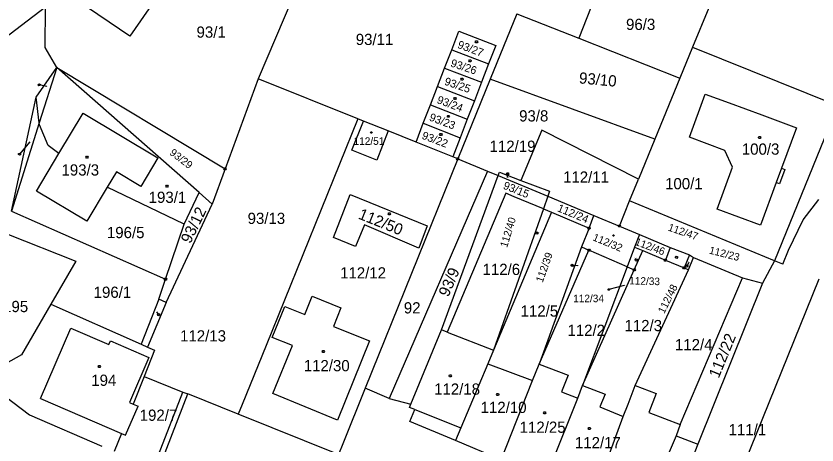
# Model space of a CAD drawing. Extents: x -634640 to -629202, y -1196156 to -1190068.
# Drawn here: x -631489.7 to -631368.4, y -1192793.1 to -1192728.1 of the extents above; entities that cross this region are included whole.
import ezdxf

# ---------------------------------------------------------------- set-up
doc = ezdxf.new("R2010")
doc.units = 0
for name, color, linetype in [('Vrstva 1', 7, 'Continuous'), ('Vrstva 2', 7, 'Continuous'), ('Vrstva 3', 7, 'Continuous'), ('Vrstva 4', 7, 'Continuous'), ('Vrstva 5', 7, 'Continuous'), ('Vrstva 7', 7, 'Continuous'), ('Vrstva 8', 7, 'Continuous')]:
    doc.layers.add(name, color=color, linetype=linetype)

msp = doc.modelspace()

# ---------------------------------------------------------------- linework, layer by layer
at = {"layer": 'Vrstva 1'}
for p, q in [((-631400.34, -1192720.95), (-631404.48, -1192731.49)), ((-631446.43, -1192722.09), (-631453.01, -1192737.63)), ((-631498.79, -1192737.08), (-631485.2, -1192726.74)), ((-631485.26, -1192732.88), (-631485.2, -1192726.74)), ((-631384.81, -1192726.88), (-631387.28, -1192732.83)), ((-631413.88, -1192727.78), (-631417.89, -1192737.71)), ((-631413.88, -1192727.78), (-631404.48, -1192731.49)), ((-631423.71, -1192733.23), (-631422.63, -1192730.43)), ((-631422.63, -1192730.43), (-631417.06, -1192732.57)), ((-631404.48, -1192731.49), (-631389.22, -1192737.52)), ((-631483.51, -1192735.91), (-631485.26, -1192732.88)), ((-631424.79, -1192736.02), (-631423.71, -1192733.23)), ((-631423.71, -1192733.23), (-631418.14, -1192735.39)), ((-631417.06, -1192732.57), (-631418.14, -1192735.39)), ((-631387.28, -1192732.83), (-631389.22, -1192737.52)), ((-631387.28, -1192732.83), (-631365.33, -1192741.7)), ((-631486.64, -1192740.44), (-631483.51, -1192735.91)), ((-631483.51, -1192735.91), (-631486.14, -1192744.29)), ((-631483.51, -1192735.91), (-631458.03, -1192751.28)), ((-631461.95, -1192754.88), (-631483.51, -1192735.91)), ((-631418.14, -1192735.39), (-631419.21, -1192738.17)), ((-631425.86, -1192738.79), (-631424.79, -1192736.02)), ((-631424.79, -1192736.02), (-631419.21, -1192738.17)), ((-631453.01, -1192737.63), (-631458.03, -1192751.28)), ((-631437.91, -1192743.69), (-631453.01, -1192737.63)), ((-631417.89, -1192737.71), (-631422.82, -1192749.75)), ((-631419.21, -1192738.17), (-631420.28, -1192740.95)), ((-631392.98, -1192746.79), (-631417.89, -1192737.71)), ((-631389.22, -1192737.52), (-631392.98, -1192746.79)), ((-631426.94, -1192741.6), (-631425.86, -1192738.79)), ((-631425.86, -1192738.79), (-631420.28, -1192740.95)), ((-631490.35, -1192757.69), (-631486.64, -1192740.44)), ((-631486.14, -1192744.29), (-631486.64, -1192740.44)), ((-631387.75, -1192746.48), (-631385.35, -1192739.94)), ((-631385.35, -1192739.94), (-631381.73, -1192741.27)), ((-631428.02, -1192744.38), (-631426.94, -1192741.6)), ((-631426.94, -1192741.6), (-631421.36, -1192743.76)), ((-631420.28, -1192740.95), (-631421.36, -1192743.76)), ((-631381.73, -1192741.27), (-631376.81, -1192743.11)), ((-631365.33, -1192741.7), (-631374.86, -1192765.19)), ((-631376.81, -1192743.11), (-631371.55, -1192745.07)), ((-631486.14, -1192744.29), (-631490.35, -1192757.69)), ((-631486.1, -1192744.61), (-631486.14, -1192744.29)), ((-631437.91, -1192743.69), (-631451.81, -1192778.03)), ((-631438.85, -1192748.46), (-631437.07, -1192744.03)), ((-631437.07, -1192744.03), (-631437.91, -1192743.69)), ((-631433.32, -1192745.53), (-631437.07, -1192744.03)), ((-631429.11, -1192747.22), (-631428.02, -1192744.38)), ((-631428.02, -1192744.38), (-631422.43, -1192746.57)), ((-631421.36, -1192743.76), (-631422.43, -1192746.57)), ((-631484.8, -1192747.76), (-631486.1, -1192744.61)), ((-631433.32, -1192745.53), (-631435.06, -1192749.97)), ((-631429.11, -1192747.22), (-631433.32, -1192745.53)), ((-631410.08, -1192745.42), (-631413.24, -1192753.02)), ((-631395.43, -1192752.83), (-631410.08, -1192745.42)), ((-631371.55, -1192745.07), (-631373.8, -1192751.19)), ((-631422.43, -1192746.57), (-631423.54, -1192749.46)), ((-631392.98, -1192746.79), (-631395.43, -1192752.83)), ((-631382.39, -1192748.49), (-631387.75, -1192746.48)), ((-631483.17, -1192748.95), (-631484.8, -1192747.76)), ((-631423.54, -1192749.46), (-631429.11, -1192747.22)), ((-631435.06, -1192749.97), (-631438.85, -1192748.46)), ((-631381.23, -1192751.01), (-631382.39, -1192748.49)), ((-631422.82, -1192749.75), (-631436.8, -1192784.5)), ((-631422.82, -1192749.75), (-631423.54, -1192749.46)), ((-631422.82, -1192749.75), (-631418.32, -1192751.62)), ((-631458.03, -1192751.28), (-631459.99, -1192756.61)), ((-631418.32, -1192751.62), (-631433.21, -1192786.06)), ((-631418.32, -1192751.62), (-631416.69, -1192752.3)), ((-631383.55, -1192757.36), (-631381.23, -1192751.01)), ((-631373.31, -1192751.35), (-631374.1, -1192753.52)), ((-631373.8, -1192751.19), (-631373.31, -1192751.35)), ((-631425.27, -1192775.67), (-631416.69, -1192752.3)), ((-631416.69, -1192752.3), (-631416.5, -1192751.78)), ((-631416.69, -1192752.3), (-631409.17, -1192755.43)), ((-631416.5, -1192751.78), (-631413.24, -1192753.02)), ((-631396.8, -1192756.14), (-631395.43, -1192752.83)), ((-631475.85, -1192754.07), (-631478.93, -1192759.2)), ((-631464.23, -1192759.66), (-631475.85, -1192754.07)), ((-631413.24, -1192753.02), (-631408.9, -1192754.67)), ((-631374.6, -1192753.36), (-631376.97, -1192759.79)), ((-631374.1, -1192753.52), (-631374.6, -1192753.36)), ((-631464.23, -1192759.66), (-631461.95, -1192754.88)), ((-631459.99, -1192756.61), (-631461.95, -1192754.88)), ((-631441.61, -1192761.66), (-631439.07, -1192755.18)), ((-631439.07, -1192755.18), (-631427.43, -1192759.9)), ((-631415.55, -1192754.95), (-631424.39, -1192776.02)), ((-631414.27, -1192755.49), (-631415.55, -1192754.95)), ((-631408.9, -1192754.67), (-631409.17, -1192755.43)), ((-631409.85, -1192757.34), (-631414.27, -1192755.49)), ((-631409.17, -1192755.43), (-631409.85, -1192757.34)), ((-631409.17, -1192755.43), (-631402.19, -1192758.33)), ((-631398.35, -1192759.93), (-631396.8, -1192756.14)), ((-631374.86, -1192765.19), (-631396.8, -1192756.14)), ((-631370.55, -1192759.01), (-631368.15, -1192755.91)), ((-631490.35, -1192757.69), (-631467.04, -1192767.99)), ((-631466.96, -1192771.5), (-631459.99, -1192756.61)), ((-631409.85, -1192757.34), (-631417.4, -1192778.73)), ((-631409.85, -1192757.34), (-631408.64, -1192757.85)), ((-631376.97, -1192759.79), (-631383.55, -1192757.36)), ((-631408.64, -1192757.85), (-631417.4, -1192778.73)), ((-631408.64, -1192757.85), (-631402.93, -1192760.24)), ((-631402.93, -1192760.24), (-631402.19, -1192758.33)), ((-631402.19, -1192758.33), (-631398.35, -1192759.93)), ((-631372.74, -1192763.57), (-631370.55, -1192759.01)), ((-631467.04, -1192767.99), (-631464.23, -1192759.66)), ((-631436.9, -1192759.76), (-631438.26, -1192763.05)), ((-631428.71, -1192763.29), (-631436.9, -1192759.76)), ((-631427.43, -1192759.9), (-631428.71, -1192763.29)), ((-631398.35, -1192759.93), (-631395.31, -1192761.21)), ((-631491.08, -1192761.11), (-631480.61, -1192765.27)), ((-631402.93, -1192760.24), (-631404.06, -1192763.1)), ((-631395.31, -1192761.21), (-631396.04, -1192763.13)), ((-631395.31, -1192761.21), (-631390.68, -1192763.18)), ((-631438.26, -1192763.05), (-631441.61, -1192761.66)), ((-631404.06, -1192763.1), (-631410.49, -1192780.87)), ((-631410.49, -1192780.87), (-631402.95, -1192763.59)), ((-631404.06, -1192763.1), (-631402.95, -1192763.59)), ((-631397.17, -1192766.12), (-631402.95, -1192763.59)), ((-631396.04, -1192763.13), (-631397.17, -1192766.12)), ((-631396.1, -1192766.55), (-631394.8, -1192763.65)), ((-631396.04, -1192763.13), (-631394.8, -1192763.65)), ((-631394.8, -1192763.65), (-631391.39, -1192765.08)), ((-631390.68, -1192763.18), (-631391.39, -1192765.08)), ((-631390.68, -1192763.18), (-631387.72, -1192764.3)), ((-631373.61, -1192765.71), (-631372.74, -1192763.57)), ((-631391.39, -1192765.08), (-631388.54, -1192766.27)), ((-631387.72, -1192764.3), (-631388.54, -1192766.27)), ((-631387.88, -1192766.55), (-631387.11, -1192764.71)), ((-631387.72, -1192764.3), (-631387.11, -1192764.71)), ((-631387.11, -1192764.71), (-631379.73, -1192767.8)), ((-631480.61, -1192765.27), (-631484.4, -1192771.78)), ((-631397.17, -1192766.12), (-631403.94, -1192784.07)), ((-631397.17, -1192766.12), (-631396.1, -1192766.55)), ((-631388.54, -1192766.27), (-631387.88, -1192766.55)), ((-631374.86, -1192765.19), (-631376.69, -1192768.59)), ((-631373.61, -1192765.71), (-631374.86, -1192765.19)), ((-631403.94, -1192784.07), (-631396.1, -1192766.55)), ((-631395.95, -1192784.07), (-631387.88, -1192766.55)), ((-631468.06, -1192771.03), (-631467.04, -1192767.99)), ((-631389.17, -1192790), (-631379.73, -1192767.8)), ((-631376.69, -1192768.59), (-631386.47, -1192792.97)), ((-631368.14, -1192767.96), (-631383.56, -1192806)), ((-631379.73, -1192767.8), (-631376.69, -1192768.59)), ((-631468.06, -1192771.03), (-631470.7, -1192777.85)), ((-631466.96, -1192771.5), (-631468.06, -1192771.03)), ((-631445.97, -1192773.35), (-631444.86, -1192770.56)), ((-631444.86, -1192770.56), (-631440.48, -1192772.32)), ((-631484.4, -1192771.78), (-631488.86, -1192779.43)), ((-631484.4, -1192771.78), (-631470.7, -1192777.85)), ((-631466.96, -1192771.5), (-631469.75, -1192778.27)), ((-631450.89, -1192776.82), (-631448.99, -1192772.12)), ((-631448.99, -1192772.12), (-631445.97, -1192773.35)), ((-631440.48, -1192772.32), (-631441.6, -1192775.13)), ((-631441.6, -1192775.13), (-631436.15, -1192777.34)), ((-631429.91, -1192786.93), (-631425.27, -1192775.67)), ((-631424.39, -1192776.02), (-631425.27, -1192775.67)), ((-631447.84, -1192778.03), (-631450.89, -1192776.82)), ((-631424.39, -1192776.02), (-631417.4, -1192778.73)), ((-631470.7, -1192777.85), (-631469.75, -1192778.27)), ((-631469.75, -1192778.27), (-631468.69, -1192778.74)), ((-631451.81, -1192778.03), (-631455.42, -1192786.96)), ((-631450.82, -1192785.29), (-631447.84, -1192778.03)), ((-631436.15, -1192777.34), (-631441.02, -1192789.32)), ((-631488.86, -1192779.43), (-631492.05, -1192781.28)), ((-631468.69, -1192778.74), (-631470.27, -1192782.71)), ((-631417.4, -1192778.73), (-631418.27, -1192780.81)), ((-631418.27, -1192780.81), (-631422.34, -1192790.52)), ((-631418.27, -1192780.81), (-631411.52, -1192783.35)), ((-631411.52, -1192783.35), (-631410.49, -1192780.87)), ((-631470.27, -1192782.71), (-631471.93, -1192786.9)), ((-631470.27, -1192782.71), (-631464.4, -1192785.07)), ((-631493.95, -1192783.7), (-631487.64, -1192788.54)), ((-631416.22, -1192795.33), (-631411.52, -1192783.35)), ((-631404.64, -1192786.02), (-631403.94, -1192784.07)), ((-631468.1, -1192794.59), (-631464.4, -1192785.07)), ((-631467.72, -1192795.79), (-631463.65, -1192785.37)), ((-631464.4, -1192785.07), (-631463.65, -1192785.37)), ((-631456.02, -1192788.44), (-631463.65, -1192785.37)), ((-631441.02, -1192789.32), (-631450.82, -1192785.29)), ((-631436.8, -1192784.5), (-631440.19, -1192792.93)), ((-631433.21, -1192786.06), (-631436.8, -1192784.5)), ((-631471.93, -1192786.9), (-631471.2, -1192787.21)), ((-631433.21, -1192786.06), (-631429.91, -1192786.93)), ((-631409.38, -1192797.8), (-631404.64, -1192786.02)), ((-631473.1, -1192791.63), (-631471.2, -1192787.21)), ((-631455.42, -1192786.96), (-631456.02, -1192788.44)), ((-631430.12, -1192787.42), (-631429.91, -1192786.93)), ((-631429.31, -1192787.74), (-631430.12, -1192787.42)), ((-631430.06, -1192789.53), (-631429.31, -1192787.74)), ((-631487.64, -1192788.54), (-631476.67, -1192793.27)), ((-631440.84, -1192794.55), (-631456.02, -1192788.44)), ((-631401.38, -1192798.66), (-631397.78, -1192788.77)), ((-631423.14, -1192792.43), (-631430.06, -1192789.53)), ((-631422.34, -1192790.52), (-631423.14, -1192792.43)), ((-631389.17, -1192790), (-631389.76, -1192791.7)), ((-631473.71, -1192791.36), (-631474.79, -1192794.08)), ((-631473.71, -1192791.36), (-631473.1, -1192791.63)), ((-631389.76, -1192791.7), (-631394, -1192801.72)), ((-631389.76, -1192791.7), (-631386.47, -1192792.97)), ((-631440.19, -1192792.93), (-631440.84, -1192794.55)), ((-631416.22, -1192795.33), (-631423.14, -1192792.43)), ((-631386.47, -1192792.97), (-631390.43, -1192803.2))]:
    msp.add_line(p, q, dxfattribs=at)
for points in [[(-631470.12, -1192710.93), (-631462.2, -1192716.4), (-631472.46, -1192731.17), (-631480.39, -1192725.76), (-631470.12, -1192710.93)], [(-631483.17, -1192748.95), (-631479.51, -1192742.85), (-631468.21, -1192749.62), (-631470.79, -1192753.93), (-631474.45, -1192751.74), (-631475.85, -1192754.07)], [(-631478.93, -1192759.2), (-631486.58, -1192754.63), (-631483.17, -1192748.95)], [(-631410.49, -1192780.87), (-631406.08, -1192782.52), (-631407.09, -1192785.04), (-631404.64, -1192786.02)], [(-631403.94, -1192784.07), (-631400.5, -1192785.38), (-631401.3, -1192787.31), (-631397.78, -1192788.77)], [(-631397.78, -1192788.77), (-631397.04, -1192786.92), (-631395.95, -1192784.07)], [(-631395.95, -1192784.07), (-631392.76, -1192785.31), (-631393.87, -1192788.18), (-631389.17, -1192790)]]:
    msp.add_lwpolyline(points, dxfattribs=at)
at = {"layer": 'Vrstva 3'}
msp.add_lwpolyline([(-631466.72, -1192753.73), (-631466.63, -1192753.88), (-631466.72, -1192754.03), (-631466.9, -1192754.03), (-631466.99, -1192753.88), (-631466.9, -1192753.73), (-631466.72, -1192753.73)], dxfattribs=at)
at = {"layer": 'Vrstva 4'}
for p, q in [((-631373.8, -1192751.19), (-631374.6, -1192753.36)), ((-631485.98, -1192786.06), (-631481.38, -1192775.4)), ((-631481.38, -1192775.4), (-631475.62, -1192777.88)), ((-631475.62, -1192777.88), (-631475.38, -1192777.3)), ((-631475.38, -1192777.3), (-631469.54, -1192779.82)), ((-631469.54, -1192779.82), (-631472.48, -1192786.66)), ((-631485.98, -1192786.06), (-631473.71, -1192791.36)), ((-631472.48, -1192786.66), (-631471.93, -1192786.9)), ((-631429.31, -1192787.74), (-631422.34, -1192790.52))]:
    msp.add_line(p, q, dxfattribs=at)
at = {"layer": 'Vrstva 5'}
for points in [[(-631419.88, -1192731.9), (-631419.79, -1192732.05), (-631419.88, -1192732.2), (-631420.06, -1192732.2), (-631420.15, -1192732.05), (-631420.06, -1192731.9), (-631419.88, -1192731.9)], [(-631420.85, -1192734.75), (-631420.76, -1192734.9), (-631420.85, -1192735.05), (-631421.03, -1192735.05), (-631421.12, -1192734.9), (-631421.03, -1192734.75), (-631420.85, -1192734.75)], [(-631422.06, -1192737.52), (-631421.97, -1192737.67), (-631422.06, -1192737.82), (-631422.24, -1192737.82), (-631422.33, -1192737.67), (-631422.24, -1192737.52), (-631422.06, -1192737.52)], [(-631423.13, -1192740.45), (-631423.04, -1192740.6), (-631423.13, -1192740.75), (-631423.31, -1192740.75), (-631423.4, -1192740.6), (-631423.31, -1192740.45), (-631423.13, -1192740.45)], [(-631424.15, -1192743.17), (-631424.06, -1192743.32), (-631424.15, -1192743.47), (-631424.33, -1192743.47), (-631424.42, -1192743.32), (-631424.33, -1192743.17), (-631424.15, -1192743.17)], [(-631435.83, -1192745.67), (-631435.769, -1192745.77), (-631435.83, -1192745.87), (-631435.95, -1192745.87), (-631436.011, -1192745.77), (-631435.95, -1192745.67), (-631435.83, -1192745.67)], [(-631425.28, -1192745.93), (-631425.19, -1192746.08), (-631425.28, -1192746.23), (-631425.46, -1192746.23), (-631425.55, -1192746.08), (-631425.46, -1192745.93), (-631425.28, -1192745.93)], [(-631377.04, -1192746.39), (-631376.95, -1192746.54), (-631377.04, -1192746.69), (-631377.22, -1192746.69), (-631377.31, -1192746.54), (-631377.22, -1192746.39), (-631377.04, -1192746.39)], [(-631478.84, -1192749.34), (-631478.75, -1192749.49), (-631478.84, -1192749.64), (-631479.02, -1192749.64), (-631479.11, -1192749.49), (-631479.02, -1192749.34), (-631478.84, -1192749.34)], [(-631433.08, -1192757.94), (-631432.99, -1192758.09), (-631433.08, -1192758.24), (-631433.26, -1192758.24), (-631433.35, -1192758.09), (-631433.26, -1192757.94), (-631433.08, -1192757.94)], [(-631399.18, -1192761.27), (-631399.119, -1192761.37), (-631399.18, -1192761.47), (-631399.3, -1192761.47), (-631399.361, -1192761.37), (-631399.3, -1192761.27), (-631399.18, -1192761.27)], [(-631443.07, -1192778.78), (-631442.98, -1192778.93), (-631443.07, -1192779.08), (-631443.25, -1192779.08), (-631443.34, -1192778.93), (-631443.25, -1192778.78), (-631443.07, -1192778.78)], [(-631476.97, -1192781.07), (-631476.88, -1192781.22), (-631476.97, -1192781.37), (-631477.15, -1192781.37), (-631477.24, -1192781.22), (-631477.15, -1192781.07), (-631476.97, -1192781.07)], [(-631423.86, -1192782.49), (-631423.77, -1192782.64), (-631423.86, -1192782.79), (-631424.04, -1192782.79), (-631424.13, -1192782.64), (-631424.04, -1192782.49), (-631423.86, -1192782.49)], [(-631416.66, -1192785.31), (-631416.57, -1192785.46), (-631416.66, -1192785.61), (-631416.84, -1192785.61), (-631416.93, -1192785.46), (-631416.84, -1192785.31), (-631416.66, -1192785.31)], [(-631409.57, -1192788.08), (-631409.48, -1192788.23), (-631409.57, -1192788.38), (-631409.75, -1192788.38), (-631409.84, -1192788.23), (-631409.75, -1192788.08), (-631409.57, -1192788.08)], [(-631402.79, -1192790.43), (-631402.7, -1192790.58), (-631402.79, -1192790.73), (-631402.97, -1192790.73), (-631403.06, -1192790.58), (-631402.97, -1192790.43), (-631402.79, -1192790.43)]]:
    msp.add_lwpolyline(points, dxfattribs=at)
at = {"layer": 'Vrstva 7'}
for p, q in [((-631485.02, -1192738.82), (-631486.15, -1192738.55)), ((-631487.59, -1192747.16), (-631489.13, -1192749.05)), ((-631415.27, -1192752.6), (-631415.27, -1192752.05)), ((-631410.58, -1192761.01), (-631410.84, -1192761.01)), ((-631395.97, -1192764.83), (-631395.77, -1192765.07)), ((-631389.73, -1192764.76), (-631389.7, -1192764.66)), ((-631404.62, -1192765.96), (-631405.48, -1192765.9)), ((-631387.85, -1192765.45), (-631388.13, -1192766)), ((-631397.6, -1192768.95), (-631399.94, -1192769.54)), ((-631468.4, -1192772.94), (-631468.08, -1192773.36))]:
    msp.add_line(p, q, dxfattribs=at)
for points in [[(-631486.275, -1192738.428), (-631486.109, -1192738.375), (-631485.983, -1192738.497), (-631486.025, -1192738.672), (-631486.191, -1192738.725), (-631486.317, -1192738.603), (-631486.275, -1192738.428)], [(-631489.295, -1192749.109), (-631489.269, -1192748.936), (-631489.105, -1192748.877), (-631488.965, -1192748.991), (-631488.991, -1192749.164), (-631489.155, -1192749.223), (-631489.295, -1192749.109)], [(-631415.18, -1192751.9), (-631415.09, -1192752.05), (-631415.18, -1192752.2), (-631415.36, -1192752.2), (-631415.45, -1192752.05), (-631415.36, -1192751.9), (-631415.18, -1192751.9)], [(-631410.99, -1192760.92), (-631410.84, -1192760.83), (-631410.69, -1192760.92), (-631410.69, -1192761.1), (-631410.84, -1192761.19), (-631410.99, -1192761.1), (-631410.99, -1192760.92)], [(-631395.748, -1192765.244), (-631395.912, -1192765.181), (-631395.933, -1192765.008), (-631395.792, -1192764.896), (-631395.628, -1192764.959), (-631395.607, -1192765.132), (-631395.748, -1192765.244)], [(-631389.564, -1192764.55), (-631389.531, -1192764.722), (-631389.667, -1192764.832), (-631389.836, -1192764.77), (-631389.869, -1192764.598), (-631389.733, -1192764.488), (-631389.564, -1192764.55)], [(-631405.624, -1192765.801), (-631405.469, -1192765.72), (-631405.325, -1192765.82), (-631405.336, -1192765.999), (-631405.491, -1192766.08), (-631405.635, -1192765.98), (-631405.624, -1192765.801)], [(-631388.279, -1192766.092), (-631388.29, -1192765.917), (-631388.141, -1192765.825), (-631387.981, -1192765.908), (-631387.97, -1192766.083), (-631388.119, -1192766.175), (-631388.279, -1192766.092)], [(-631400.052, -1192769.506), (-631399.969, -1192769.423), (-631399.857, -1192769.457), (-631399.828, -1192769.574), (-631399.911, -1192769.657), (-631400.023, -1192769.623), (-631400.052, -1192769.506)], [(-631468.059, -1192773.534), (-631468.222, -1192773.471), (-631468.243, -1192773.297), (-631468.101, -1192773.186), (-631467.938, -1192773.249), (-631467.917, -1192773.423), (-631468.059, -1192773.534)]]:
    msp.add_lwpolyline(points, dxfattribs=at)
at = {"layer": 'Vrstva 8'}
for points in [[(-631422.73, -1192749.6), (-631422.64, -1192749.75), (-631422.73, -1192749.9), (-631422.91, -1192749.9), (-631423, -1192749.75), (-631422.91, -1192749.6), (-631422.73, -1192749.6)], [(-631457.94, -1192751.13), (-631457.85, -1192751.28), (-631457.94, -1192751.43), (-631458.12, -1192751.43), (-631458.21, -1192751.28), (-631458.12, -1192751.13), (-631457.94, -1192751.13)], [(-631402.84, -1192760.09), (-631402.75, -1192760.24), (-631402.84, -1192760.39), (-631403.02, -1192760.39), (-631403.11, -1192760.24), (-631403.02, -1192760.09), (-631402.84, -1192760.09)], [(-631398.26, -1192759.78), (-631398.17, -1192759.93), (-631398.26, -1192760.08), (-631398.44, -1192760.08), (-631398.53, -1192759.93), (-631398.44, -1192759.78), (-631398.26, -1192759.78)], [(-631402.86, -1192763.44), (-631402.77, -1192763.59), (-631402.86, -1192763.74), (-631403.04, -1192763.74), (-631403.13, -1192763.59), (-631403.04, -1192763.44), (-631402.86, -1192763.44)], [(-631391.3, -1192764.93), (-631391.21, -1192765.08), (-631391.3, -1192765.23), (-631391.48, -1192765.23), (-631391.57, -1192765.08), (-631391.48, -1192764.93), (-631391.3, -1192764.93)], [(-631388.45, -1192766.12), (-631388.36, -1192766.27), (-631388.45, -1192766.42), (-631388.63, -1192766.42), (-631388.72, -1192766.27), (-631388.63, -1192766.12), (-631388.45, -1192766.12)], [(-631396.01, -1192766.4), (-631395.92, -1192766.55), (-631396.01, -1192766.7), (-631396.19, -1192766.7), (-631396.28, -1192766.55), (-631396.19, -1192766.4), (-631396.01, -1192766.4)], [(-631466.95, -1192767.84), (-631466.86, -1192767.99), (-631466.95, -1192768.14), (-631467.13, -1192768.14), (-631467.22, -1192767.99), (-631467.13, -1192767.84), (-631466.95, -1192767.84)]]:
    msp.add_lwpolyline(points, dxfattribs=at)

# ---------------------------------------------------------------- texts
at = {"layer": 'Vrstva 2'}
for s, height, p in [('96/3', 1.7, (-631397.338, -1192730.24)), ('93/1', 1.7, (-631462.343, -1192731.41)), ('93/11', 1.7, (-631438.243, -1192732.52)), ('193/2', 0.1, (-631485.226, -1192738.82)), ('93/8', 1.7, (-631413.523, -1192744.1)), ('196/6', 0.1, (-631487.731, -1192746.71)), ('112/51', 1.14, (-631438.58, -1192747.64)), ('100/3', 1.7, (-631379.817, -1192749.13)), ('193/3', 1.7, (-631482.78, -1192752.29)), ('112/11', 1.7, (-631406.867, -1192753.37)), ('112/19', 0.1, (-631415.247, -1192752.6)), ('100/1', 1.7, (-631391.427, -1192754.37)), ('193/1', 1.7, (-631469.592, -1192756.43)), ('93/13', 1.7, (-631454.613, -1192759.62)), ('196/5', 1.7, (-631475.91, -1192761.77)), ('112/40', 0.1, (-631410.819, -1192761.01)), ('112/33', 0.1, (-631396.207, -1192764.83)), ('112/47', 0.1, (-631389.969, -1192764.76)), ('112/12', 1.7, (-631440.617, -1192767.88)), ('112/6', 1.7, (-631419.057, -1192767.35)), ('112/39', 0.1, (-631404.854, -1192765.96)), ('112/48', 0.1, (-631388.089, -1192765.45)), ('196/1', 1.7, (-631477.917, -1192770.81)), ('112/34', 0.1, (-631397.839, -1192768.95)), ('195', 1.7, (-631491.617, -1192772.97)), ('92', 1.7, (-631430.969, -1192773.17)), ('112/5', 1.7, (-631413.297, -1192773.65)), ('112/13', 0.1, (-631468.377, -1192772.94)), ('112/3', 1.7, (-631397.577, -1192775.86)), ('112/2', 1.7, (-631406.207, -1192776.58)), ('112/4', 1.7, (-631389.937, -1192778.75)), ('112/30', 1.7, (-631446.117, -1192781.93)), ('194', 1.7, (-631478.277, -1192784.14)), ('112/18', 1.7, (-631426.387, -1192785.48)), ('112/10', 1.7, (-631419.347, -1192788.25)), ('192/7', 1.7, (-631470.947, -1192789.43)), ('112/25', 1.7, (-631413.437, -1192791.25)), ('111/1', 1.7, (-631381.817, -1192791.62)), ('112/17', 1.7, (-631405.077, -1192793.59))]:
    msp.add_text(s, height=height, dxfattribs=at).set_placement(p)
for s, height, rotation, p in [('93/27', 1.2, 339.82127, (-631422.943, -1192732.928)), ('93/26', 1.2, 341.71203, (-631423.991, -1192735.743)), ('93/10', 1.7, 354.71817, (-631404.514, -1192738.322)), ('93/25', 1.2, 341.19637, (-631424.931, -1192738.504)), ('93/24', 1.2, 339.4202, (-631426.053, -1192741.279)), ('93/23', 1.2, 339.4202, (-631427.223, -1192743.919)), ('93/22', 1.2, 339.3629, (-631428.343, -1192746.679)), ('93/29', 1.14, 322.40335, (-631466.514, -1192749.024)), ('93/15', 1.2, 338.33158, (-631416.034, -1192754.252)), ('93/12', 1.7, 64.05668, (-631463.286, -1192762.707)), ('112/50', 1.7, 338.0451, (-631437.984, -1192758.779)), ('112/24', 1.2, 337.47214, (-631407.844, -1192757.656)), ('112/32', 1.14, 337.41484, (-631402.48, -1192762.064)), ('112/46', 1.14, 339.3629, (-631396.074, -1192762.759)), ('112/23', 1.14, 345.60814, (-631384.845, -1192764.085)), ('93/9', 1.7, 66.74958, (-631424.226, -1192770.772)), ('112/22', 1.7, 67.60902, (-631383.31, -1192783.077))]:
    msp.add_text(s, height=height, rotation=rotation, dxfattribs=at).set_placement(p)
at = {"layer": 'Vrstva 7'}
for s, height, p in [('112/19', 1.7, (-631417.997, -1192748.7)), ('112/34', 1.14, (-631405.344, -1192771.47)), ('112/13', 1.7, (-631464.837, -1192777.42))]:
    msp.add_text(s, height=height, dxfattribs=at).set_placement(p)
for s, rotation, p in [('112/40', 73.16671, (-631415.338, -1192763.273)), ('112/47', 341.02448, (-631391.08, -1192760.593)), ('112/39', 70.47381, (-631409.963, -1192768.577)), ('112/33', 358.27051, (-631396.876, -1192768.759)), ('112/48', 63.42643, (-631391.559, -1192773.296))]:
    msp.add_text(s, height=1.14, rotation=rotation, dxfattribs=at).set_placement(p)

doc.saveas('drawing.dxf')
